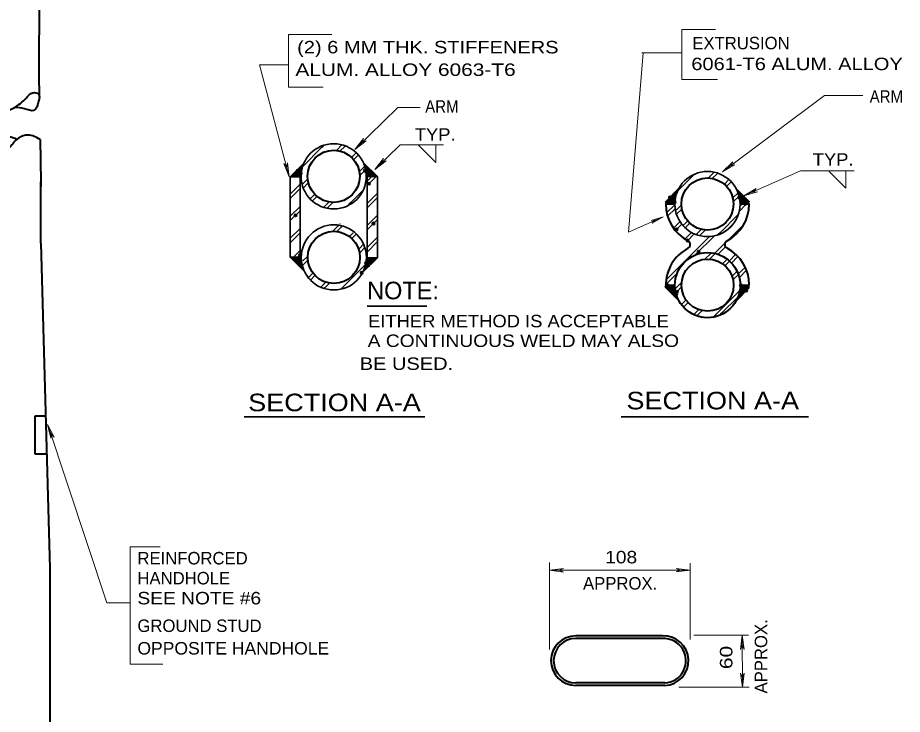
# Model space of a CAD drawing. Extents: x 312583 to 312854, y 144418 to 144597.
# Drawn here: x 312635.8 to 312689.7, y 144489.4 to 144531.9 of the extents above; entities that cross this region are included whole.
import ezdxf
from ezdxf.enums import TextEntityAlignment as Align

# ---------------------------------------------------------------- set-up
doc = ezdxf.new("R2010")
doc.units = 0
doc.header["$LTSCALE"] = 0.3
doc.header["$PDMODE"] = 32
doc.header["$PDSIZE"] = 0.15
doc.layers.add('1', color=7, linetype='Continuous', lineweight=35)

msp = doc.modelspace()

# ---------------------------------------------------------------- linework, layer by layer
at = {"layer": '1', "lineweight": 40}
for p, q in [((312637.0871, 144547.1518), (312637.0642, 144528.44)), ((312637.0642, 144528.44), (312637.0795, 144526.9989)), ((312637.1481, 144524.4369), (312637.1786, 144521.8597)), ((312656.8302, 144523.0071), (312656.8455, 144523.0224)), ((312656.8531, 144522.9385), (312656.8912, 144522.9766)), ((312656.876, 144522.8699), (312656.937, 144522.9309)), ((312652.4535, 144522.1608), (312653.155, 144522.8622)), ((312652.545, 144522.1608), (312653.1016, 144522.7174)), ((312652.6365, 144522.1608), (312653.0635, 144522.5878)), ((312652.7356, 144522.1608), (312653.033, 144522.4658)), ((312656.9065, 144522.8012), (312656.9904, 144522.8851)), ((312656.9294, 144522.7326), (312657.0361, 144522.8394)), ((312656.9522, 144522.664), (312657.0818, 144522.7936)), ((312656.9675, 144522.5878), (312657.1276, 144522.7479)), ((312656.9827, 144522.5039), (312657.1734, 144522.6945)), ((312656.9904, 144522.42), (312657.2191, 144522.6488)), ((312656.998, 144522.3361), (312657.2648, 144522.603)), ((312656.998, 144522.2446), (312657.3106, 144522.5572)), ((312657.0361, 144522.1836), (312657.364, 144522.5115)), ((312657.1276, 144522.1836), (312657.4097, 144522.4658)), ((312657.2191, 144522.1836), (312657.4555, 144522.42)), ((312657.3106, 144522.1836), (312657.5012, 144522.3666)), ((312637.171, 144518.1234), (312637.1786, 144521.8597)), ((312637.1786, 144521.8597), (312637.1862, 144521.5699)), ((312652.8271, 144522.1608), (312653.0254, 144522.359)), ((312652.9186, 144522.1608), (312653.0101, 144522.2522)), ((312657.4021, 144522.1836), (312657.547, 144522.3209)), ((312657.4936, 144522.176), (312657.5927, 144522.2751)), ((312657.5927, 144522.176), (312657.6385, 144522.2294)), ((312657.6842, 144522.176), (312657.6842, 144522.1836)), ((312675.2294, 144520.6281), (312676.0681, 144521.4745)), ((312679.568, 144521.3906), (312679.5832, 144521.4059)), ((312679.5908, 144521.3296), (312679.629, 144521.3601)), ((312679.6214, 144521.261), (312679.6747, 144521.3144)), ((312675.2294, 144520.5366), (312675.9766, 144521.2839)), ((312675.2904, 144520.5061), (312675.9156, 144521.1314)), ((312675.3818, 144520.5061), (312675.8622, 144520.9865)), ((312675.4734, 144520.5061), (312675.8394, 144520.8721)), ((312675.5725, 144520.5061), (312675.8165, 144520.7501)), ((312679.6518, 144521.2), (312679.7205, 144521.2686)), ((312679.6824, 144521.1314), (312679.7662, 144521.2229)), ((312679.6976, 144521.0551), (312679.812, 144521.1771)), ((312679.7128, 144520.9789), (312679.8577, 144521.1238)), ((312679.7281, 144520.9026), (312679.9111, 144521.078)), ((312679.7434, 144520.8188), (312679.9568, 144521.0322)), ((312679.7586, 144520.7425), (312680.0026, 144520.9865)), ((312679.7662, 144520.6586), (312680.0484, 144520.9408)), ((312679.7738, 144520.5748), (312680.0941, 144520.895)), ((312679.7891, 144520.4985), (312680.1398, 144520.8492)), ((312679.8882, 144520.4985), (312680.1856, 144520.8035)), ((312679.9797, 144520.4985), (312680.2314, 144520.7501)), ((312675.664, 144520.5061), (312675.8088, 144520.651)), ((312675.7555, 144520.5061), (312675.7936, 144520.5442)), ((312680.0712, 144520.4985), (312680.2847, 144520.7044)), ((312680.2618, 144520.4985), (312680.3457, 144520.5824)), ((312637.171, 144518.1234), (312637.72, 144498.2908)), ((312652.3848, 144517.2426), (312652.4077, 144517.2579)), ((312652.4306, 144517.1969), (312652.4992, 144517.2579)), ((312652.484, 144517.1511), (312652.5907, 144517.2579)), ((312652.5297, 144517.1054), (312652.6822, 144517.2579)), ((312652.5755, 144517.0596), (312652.7814, 144517.2579)), ((312652.6212, 144517.0062), (312652.8728, 144517.2579)), ((312652.667, 144516.9605), (312652.9644, 144517.2579)), ((312652.7127, 144516.9148), (312653.0254, 144517.2274)), ((312652.7585, 144516.869), (312653.0482, 144517.1588)), ((312652.8042, 144516.8232), (312653.0558, 144517.0749)), ((312652.8576, 144516.7775), (312653.0711, 144516.991)), ((312656.8531, 144516.4801), (312657.608, 144517.235)), ((312656.9141, 144516.6326), (312657.5165, 144517.235)), ((312656.9446, 144516.7546), (312657.425, 144517.235)), ((312656.9751, 144516.8766), (312657.3258, 144517.235)), ((312657.0056, 144517.0978), (312657.1428, 144517.235)), ((312657.0056, 144517.1969), (312657.0437, 144517.2274)), ((312657.0208, 144517.0215), (312657.2344, 144517.235)), ((312652.9034, 144516.7318), (312653.0787, 144516.9071)), ((312652.9491, 144516.6784), (312653.0864, 144516.8156)), ((312652.9948, 144516.6326), (312653.1092, 144516.7546)), ((312653.0406, 144516.5869), (312653.1397, 144516.686)), ((312653.0864, 144516.5411), (312653.1626, 144516.6174)), ((312653.1321, 144516.4954), (312653.1855, 144516.5488)), ((312653.1778, 144516.4496), (312653.216, 144516.4801)), ((312653.2312, 144516.4039), (312653.2465, 144516.4191)), ((312675.2217, 144515.4889), (312675.298, 144515.5651)), ((312675.4276, 144515.2296), (312675.7631, 144515.5651)), ((312675.481, 144515.1839), (312675.8088, 144515.5194)), ((312675.5267, 144515.1381), (312675.8088, 144515.4279)), ((312679.5527, 144514.6272), (312680.361, 144515.4431)), ((312679.6366, 144514.8102), (312680.361, 144515.5346)), ((312679.6976, 144514.9628), (312680.3, 144515.5651)), ((312679.7205, 144515.0771), (312680.2008, 144515.5651)), ((312679.751, 144515.1991), (312680.1094, 144515.5651)), ((312679.7586, 144515.3059), (312680.0178, 144515.5651)), ((312679.7738, 144515.4126), (312679.9264, 144515.5651)), ((312679.7967, 144515.527), (312679.8272, 144515.5651)), ((312675.5725, 144515.0924), (312675.8241, 144515.344)), ((312675.6182, 144515.0466), (312675.8317, 144515.2601)), ((312675.664, 144515.0009), (312675.8546, 144515.1839)), ((312675.7097, 144514.9551), (312675.8698, 144515.1152)), ((312675.7555, 144514.9094), (312675.8927, 144515.039)), ((312675.8088, 144514.856), (312675.9156, 144514.9628)), ((312675.8546, 144514.8102), (312675.9308, 144514.8941)), ((312675.9004, 144514.7645), (312675.9537, 144514.8255)), ((312675.9461, 144514.7188), (312675.9842, 144514.7569)), ((312675.9918, 144514.673), (312676.0071, 144514.6882)), ((312636.8202, 144507.5857), (312636.8202, 144505.2829)), ((312637.4608, 144507.5857), (312636.8202, 144507.5857)), ((312636.8202, 144505.2829), (312637.5218, 144505.2829)), ((312637.72, 144498.2908), (312637.72, 144477.8024)), ((312675.0624, 144494.1835), (312669.7707, 144494.1911)), ((312675.0624, 144494.0234), (312669.7707, 144494.031)), ((312675.1997, 144491.3241), (312669.7707, 144491.3318)), ((312675.1997, 144491.1716), (312669.7707, 144491.1716))]:
    msp.add_line(p, q, dxfattribs=at)
at = {"layer": '1', "lineweight": 13}
for p, q in [((312676.2376, 144528.0969), (312676.2376, 144531.1469)), ((312676.2376, 144531.1469), (312678.2887, 144531.1469)), ((312652.2781, 144527.6279), (312652.2781, 144530.8456)), ((312652.2781, 144530.8456), (312654.9164, 144530.8456)), ((312673.8645, 144529.7185), (312672.98, 144518.7829)), ((312676.2376, 144529.7185), (312673.796, 144529.7185)), ((312676.2376, 144528.0969), (312678.3955, 144528.0969)), ((312652.2781, 144527.6279), (312654.3902, 144527.6279)), ((312656.3041, 144523.823), (312656.8455, 144524.5016)), ((312656.3041, 144523.823), (312656.998, 144524.3491)), ((312656.8455, 144524.5016), (312656.7235, 144524.2348)), ((312656.998, 144524.3491), (312656.7235, 144524.2348)), ((312659.0644, 144524.1204), (312657.5241, 144522.603)), ((312661.7026, 144524.1204), (312659.0644, 144524.1204)), ((312651.9884, 144522.969), (312652.1637, 144522.7326)), ((312652.3162, 144522.1684), (312651.9884, 144522.969)), ((312652.2018, 144523.0224), (312652.1637, 144522.7326)), ((312652.3162, 144522.1684), (312652.2018, 144523.0224)), ((312657.5241, 144522.603), (312658.0578, 144523.2816)), ((312657.5241, 144522.603), (312658.2104, 144523.1291)), ((312658.0578, 144523.2816), (312657.9358, 144523.0148)), ((312658.2104, 144523.1291), (312657.9358, 144523.0148)), ((312678.7064, 144522.4734), (312679.3316, 144523.0681)), ((312679.3316, 144523.0681), (312679.1715, 144522.8241)), ((312678.7064, 144522.4734), (312679.4536, 144522.9004)), ((312679.4536, 144522.9004), (312679.1715, 144522.8241)), ((312683.4644, 144522.5344), (312680.0026, 144521.0018)), ((312686.7278, 144522.5344), (312683.4644, 144522.5344)), ((312685.2028, 144522.4962), (312686.217, 144521.4821)), ((312686.217, 144522.5344), (312686.217, 144521.4821)), ((312652.3696, 144522.1608), (312652.3391, 144522.1836)), ((312680.0026, 144521.0018), (312680.7498, 144521.444)), ((312680.7498, 144521.444), (312680.5364, 144521.2381)), ((312680.0026, 144521.0018), (312680.8337, 144521.2534)), ((312680.8337, 144521.2534), (312680.5364, 144521.2381)), ((312672.98, 144518.7829), (312675.0845, 144519.7284)), ((312675.0845, 144519.7284), (312674.3525, 144519.4996)), ((312675.0845, 144519.7284), (312674.4287, 144519.3319)), ((312674.3525, 144519.4996), (312674.6117, 144519.5149)), ((312674.4287, 144519.3319), (312674.6117, 144519.5149)), ((312637.5904, 144507.0748), (312637.7962, 144506.2284)), ((312637.5904, 144507.0748), (312637.9945, 144506.3047)), ((312641.197, 144496.2016), (312637.6285, 144506.9986)), ((312637.7962, 144506.2284), (312637.7962, 144506.5258)), ((312637.9945, 144506.3047), (312637.7962, 144506.5258)), ((312642.6229, 144499.6252), (312642.6229, 144492.4729)), ((312642.6229, 144499.6252), (312644.4452, 144499.6252)), ((312668.1618, 144493.3676), (312668.1618, 144498.6594)), ((312668.1618, 144498.1866), (312669.0234, 144498.2934)), ((312676.74, 144498.1942), (312668.1618, 144498.1866)), ((312668.1618, 144498.1866), (312669.0234, 144498.0799)), ((312669.0234, 144498.2934), (312668.749, 144498.1866)), ((312669.0234, 144498.0799), (312668.749, 144498.1866)), ((312675.8783, 144498.301), (312676.1528, 144498.1942)), ((312676.74, 144498.1942), (312675.8783, 144498.301)), ((312675.8783, 144498.0875), (312676.1528, 144498.1942)), ((312676.74, 144498.1942), (312675.8783, 144498.0875)), ((312676.7476, 144493.97), (312676.74, 144498.6289)), ((312641.197, 144496.2016), (312642.6229, 144496.2016)), ((312680.2932, 144494.2292), (312676.9534, 144494.2292)), ((312679.912, 144494.2292), (312679.8128, 144493.3676)), ((312679.9196, 144491.0649), (312679.912, 144494.2292)), ((312679.912, 144494.2292), (312680.0263, 144493.3676)), ((312679.8128, 144493.3676), (312679.912, 144493.6421)), ((312680.0263, 144493.3676), (312679.912, 144493.6421)), ((312642.6229, 144492.4729), (312644.6054, 144492.4729)), ((312679.8128, 144491.9265), (312679.9196, 144491.652)), ((312679.9196, 144491.0649), (312679.8128, 144491.9265)), ((312680.0263, 144491.9265), (312679.9196, 144491.652)), ((312679.9196, 144491.0649), (312680.0263, 144491.9265)), ((312680.3313, 144491.0649), (312676.0384, 144491.0649))]:
    msp.add_line(p, q, dxfattribs=at)
at = {"layer": '1'}
for p, q in [((312654.2911, 144523.9602), (312654.4207, 144524.0899)), ((312655.1908, 144523.7772), (312655.5416, 144524.128)), ((312655.4196, 144523.7391), (312655.6788, 144523.9984)), ((312655.6636, 144523.9831), (312655.7322, 144524.0441)), ((312653.1321, 144522.7936), (312654.3064, 144523.9755)), ((312656.1135, 144523.3502), (312656.3498, 144523.5942)), ((312656.2431, 144523.213), (312656.4871, 144523.457)), ((312656.3422, 144523.579), (312656.388, 144523.6324)), ((312656.4642, 144523.4341), (312656.5252, 144523.4951)), ((312652.3696, 144522.1608), (312653.2312, 144523.0224)), ((312657.6918, 144522.176), (312656.8226, 144523.0452)), ((312656.5786, 144522.4734), (312656.8684, 144522.7631)), ((312656.6167, 144522.237), (312656.9065, 144522.5344)), ((312656.8455, 144522.7326), (312656.9065, 144522.8012)), ((312656.8988, 144522.5191), (312656.9675, 144522.5878)), ((312677.86, 144522.0998), (312678.2031, 144522.4429)), ((312678.3556, 144522.3209), (312678.4166, 144522.3895)), ((312652.3696, 144517.2579), (312652.3696, 144522.1608)), ((312652.3696, 144522.1608), (312652.972, 144522.1608)), ((312652.972, 144517.2579), (312652.972, 144522.1608)), ((312657.059, 144517.235), (312657.059, 144522.176)), ((312657.059, 144522.176), (312657.6918, 144522.176)), ((312657.059, 144521.627), (312657.608, 144522.176)), ((312657.059, 144521.8939), (312657.3411, 144522.176)), ((312657.6918, 144517.235), (312657.6918, 144522.176)), ((312675.9614, 144521.2839), (312676.8764, 144522.1989)), ((312676.8458, 144522.1608), (312677.0136, 144522.3361)), ((312678.0811, 144522.054), (312678.3785, 144522.3438)), ((312678.8207, 144521.7109), (312679.1028, 144521.993)), ((312652.3696, 144521.1085), (312652.972, 144521.7109)), ((312652.3696, 144520.8416), (312652.972, 144521.444)), ((312653.1626, 144521.4821), (312653.4905, 144521.81)), ((312655.9762, 144520.5214), (312656.8302, 144521.3678)), ((312675.2294, 144520.6434), (312676.0834, 144521.505)), ((312678.958, 144521.5812), (312679.1944, 144521.8176)), ((312680.3457, 144520.6434), (312679.5451, 144521.444)), ((312653.582, 144520.8264), (312653.8641, 144521.1085)), ((312653.7192, 144520.6891), (312654.0014, 144520.9712)), ((312657.059, 144520.5442), (312657.6918, 144521.1771)), ((312657.059, 144520.2774), (312657.6918, 144520.9102)), ((312679.3316, 144520.8798), (312679.6518, 144521.1924)), ((312679.3774, 144520.651), (312679.6747, 144520.9484)), ((312679.6518, 144520.9255), (312679.7128, 144520.9865)), ((312652.3696, 144519.7589), (312652.972, 144520.3612)), ((312654.4131, 144520.3079), (312654.741, 144520.6358)), ((312654.6266, 144520.2469), (312654.9774, 144520.5976)), ((312655.8466, 144520.3841), (312656.0448, 144520.59)), ((312675.2294, 144520.5061), (312675.7936, 144520.5061)), ((312675.298, 144519.9648), (312675.7936, 144520.4528)), ((312675.3437, 144519.736), (312675.8394, 144520.2316)), ((312675.908, 144520.1478), (312676.1901, 144520.4299)), ((312679.7128, 144520.0562), (312680.1551, 144520.5061)), ((312679.7891, 144520.407), (312679.8806, 144520.4985)), ((312680.3457, 144520.4985), (312679.812, 144520.4985)), ((312652.3696, 144519.492), (312652.972, 144520.0944)), ((312657.059, 144519.1946), (312657.6918, 144519.8351)), ((312675.847, 144520.0868), (312675.9232, 144520.163)), ((312675.908, 144519.8809), (312676.2282, 144520.2011)), ((312678.5386, 144518.7295), (312679.6671, 144519.8656)), ((312655.3281, 144519.2251), (312654.9316, 144518.821)), ((312655.2061, 144518.8286), (312655.534, 144519.1565)), ((312655.2442, 144519.1336), (312655.3205, 144519.2175)), ((312655.412, 144519.3014), (312655.4044, 144519.3014)), ((312655.4806, 144519.1031), (312655.5416, 144519.1718)), ((312657.059, 144518.9278), (312657.6918, 144519.5606)), ((312675.7097, 144519.0192), (312676.1215, 144519.431)), ((312675.8241, 144518.8668), (312676.2282, 144519.2709)), ((312676.2968, 144519.1946), (312676.3578, 144519.2556)), ((312676.335, 144519.2251), (312676.579, 144519.4691)), ((312676.4341, 144519.0574), (312676.7162, 144519.3319)), ((312680.0178, 144519.2785), (312679.0037, 144518.272)), ((312679.019, 144518.9506), (312679.3468, 144519.2709)), ((312652.3696, 144518.4169), (312652.972, 144519.0116)), ((312652.3696, 144518.1424), (312652.972, 144518.7448)), ((312656.2126, 144518.76), (312655.9838, 144518.5312)), ((312656.1211, 144518.4016), (312656.4032, 144518.6838)), ((312676.4112, 144518.3711), (312676.8154, 144518.7752)), ((312676.5714, 144518.2644), (312676.9907, 144518.6838)), ((312677.0975, 144518.6456), (312677.1585, 144518.7066)), ((312677.1432, 144518.6838), (312677.4254, 144518.9659)), ((312677.3034, 144518.577), (312677.6465, 144518.9201)), ((312678.4318, 144518.6228), (312678.5767, 144518.7752)), ((312657.059, 144517.8526), (312657.6918, 144518.4855)), ((312657.059, 144517.5781), (312657.6918, 144518.2186)), ((312675.2598, 144515.8701), (312677.9057, 144518.5236)), ((312677.0517, 144517.4028), (312678.2031, 144518.5465)), ((312678.8741, 144518.1424), (312678.2336, 144517.5019)), ((312652.5678, 144517.2579), (312652.972, 144517.6696)), ((312656.5481, 144517.7459), (312656.8455, 144518.0509)), ((312656.6091, 144517.54), (312656.9217, 144517.8526)), ((312677.9438, 144517.4561), (312678.0277, 144517.5324)), ((312678.4471, 144517.4485), (312678.8741, 144517.8755)), ((312652.3696, 144517.2579), (312652.972, 144517.2579)), ((312652.3696, 144517.2579), (312653.2694, 144516.3658)), ((312652.8347, 144517.2579), (312652.972, 144517.3951)), ((312653.1092, 144516.7394), (312653.4524, 144517.0825)), ((312653.4447, 144517.3341), (312653.1474, 144517.0444)), ((312657.6918, 144517.235), (312656.8226, 144516.3658)), ((312657.059, 144517.235), (312657.6918, 144517.235)), ((312677.6388, 144517.1511), (312677.9667, 144517.479)), ((312677.9057, 144517.1511), (312678.2565, 144517.4942)), ((312678.7064, 144516.869), (312678.9427, 144517.1054)), ((312678.8588, 144516.747), (312679.1334, 144517.0291)), ((312678.9275, 144517.0901), (312678.9885, 144517.1511)), ((312679.1257, 144517.0444), (312679.507, 144517.4256)), ((312679.2554, 144516.9071), (312679.629, 144517.2808)), ((312655.5035, 144515.3516), (312656.9675, 144516.8156)), ((312679.6671, 144516.2438), (312680.0788, 144516.6479)), ((312679.7357, 144516.0379), (312680.1704, 144516.4725)), ((312653.4752, 144516.0226), (312653.5286, 144516.076)), ((312653.765, 144516.3124), (312653.4828, 144516.0302)), ((312653.5972, 144515.8778), (312653.6582, 144515.9311)), ((312653.6201, 144515.893), (312653.8717, 144516.1522)), ((312675.2217, 144515.5651), (312675.969, 144516.3124)), ((312679.2858, 144516.0989), (312679.5527, 144516.3658)), ((312679.3545, 144515.9006), (312679.6747, 144516.2209)), ((312679.5298, 144516.3505), (312679.5908, 144516.4115)), ((312654.2377, 144515.4355), (312654.5427, 144515.7405)), ((312654.2377, 144515.4355), (312654.3064, 144515.5041)), ((312654.4284, 144515.3592), (312654.4894, 144515.4202)), ((312654.436, 144515.3669), (312654.7562, 144515.6871)), ((312655.4654, 144515.3135), (312655.6026, 144515.4584)), ((312675.2217, 144515.5651), (312675.7784, 144515.5651)), ((312675.2217, 144515.4431), (312676.03, 144514.6349)), ((312675.8241, 144515.3364), (312676.213, 144515.7252)), ((312675.9156, 144515.161), (312676.2054, 144515.4508)), ((312680.361, 144515.4279), (312679.5298, 144514.5968)), ((312680.361, 144515.5651), (312679.8044, 144515.5651)), ((312680.3381, 144515.5651), (312680.361, 144515.588)), ((312675.8698, 144515.1076), (312675.9308, 144515.1762)), ((312678.1421, 144513.6131), (312679.6747, 144515.1458)), ((312678.6454, 144513.8495), (312679.6518, 144514.8484)), ((312679.6518, 144515.1152), (312679.751, 144515.222)), ((312657.0639, 144514.2808), (312660.701, 144514.2808)), ((312676.213, 144514.3756), (312676.5027, 144514.6654)), ((312676.3655, 144514.2612), (312676.6095, 144514.4976)), ((312676.335, 144514.2231), (312676.3884, 144514.2765)), ((312676.9526, 144513.7656), (312677.2576, 144514.0706)), ((312677.1432, 144513.6894), (312677.2118, 144513.758)), ((312677.189, 144513.7351), (312677.4711, 144514.0172)), ((312678.5157, 144513.7122), (312678.6758, 144513.8724)), ((312649.5759, 144507.5436), (312660.5714, 144507.5436)), ((312672.5423, 144507.5436), (312683.9368, 144507.5436))]:
    msp.add_line(p, q, dxfattribs=at)
at = {"layer": '1', "lineweight": 13}
for points in [[(312652.2781, 144528.9851), (312650.4938, 144528.9851), (312652.3162, 144522.1684)], [(312687.254, 144527.1246), (312684.9207, 144527.1246), (312678.7064, 144522.4734)], [(312660.292, 144526.385), (312658.9195, 144526.385), (312656.3041, 144523.823)], [(312660.1776, 144524.1204), (312661.2527, 144523.0376), (312661.2527, 144524.1204)]]:
    msp.add_lwpolyline(points, dxfattribs=at)
at = {"layer": '1'}
for points in [[(312653.1474, 144521.7338), (312653.1016, 144521.688), (312653.4447, 144522.0388)], [(312679.1791, 144521.8024), (312679.2401, 144521.8634), (312679.2401, 144521.8634)]]:
    msp.add_lwpolyline(points, dxfattribs=at)
at = {"layer": '1', "lineweight": 40}
for points in [[(312680.1704, 144520.4985), (312680.3305, 144520.6586), (312680.3305, 144520.6586)], [(312675.2446, 144515.4202), (312675.2446, 144515.4202), (312675.3895, 144515.5651)], [(312675.2904, 144515.3745), (312675.2904, 144515.3745), (312675.481, 144515.5651)], [(312675.3361, 144515.3288), (312675.3361, 144515.3288), (312675.5801, 144515.5651)], [(312675.3818, 144515.2754), (312675.3818, 144515.2754), (312675.6716, 144515.5651)]]:
    msp.add_lwpolyline(points, dxfattribs=at)
at = {"layer": '1'}
for centre in [(312655.0206, 144522.1938), (312677.7901, 144520.5049), (312655.0288, 144517.2534)]:
    msp.add_circle(centre, 1.9857, dxfattribs=at)
at = {"layer": '1', "lineweight": 40}
for centre, radius in [((312655.0206, 144522.1938), 1.5885), ((312677.7901, 144520.5049), 1.5885), ((312655.0288, 144517.2534), 1.5885), ((312677.7983, 144515.5645), 1.9857), ((312677.7983, 144515.5645), 1.5885)]:
    msp.add_circle(centre, radius, dxfattribs=at)
for centre, radius, start, end in [((312677.7901, 144520.5049), 2.5417, 179.98549, 242.16622), ((312677.7901, 144520.5049), 2.5417, 298.02538, 359.64884), ((312676.4847, 144518.0325), 0.2542, 298.02537, 62.16622), ((312679.1037, 144518.0369), 0.2542, 118.02538, 242.16622), ((312677.7983, 144515.5645), 2.5417, 118.02538, 180.9673), ((312677.7983, 144515.5645), 2.5417, 0.19598, 62.16622), ((312669.7685, 144492.6811), 1.5091, 89.96381, 269.9397), ((312669.7685, 144492.6811), 1.3503, 89.95955, 269.93261), ((312675.1279, 144492.6769), 1.511, 272.74469, 92.55551), ((312675.1279, 144492.6769), 1.3521, 272.74469, 92.85568)]:
    msp.add_arc(centre, radius, start, end, dxfattribs=at)
for points in [[(312634.1896, 144526.6634), (312634.7844, 144526.183), (312635.5088, 144526.3432), (312635.9358, 144526.6406), (312636.2865, 144526.9608), (312636.6906, 144527.281), (312637.0414, 144527.2048), (312637.0414, 144526.7702), (312636.744, 144526.2059), (312636.1798, 144526.3127), (312635.6155, 144526.3966)], [(312637.1481, 144524.4369), (312636.4085, 144524.7114), (312635.8138, 144524.5208), (312635.524, 144524.2539), (312635.3105, 144523.987), (312635.036, 144523.8803), (312634.4184, 144523.8803), (312634.1515, 144524.1167), (312634.2888, 144524.4369), (312634.6929, 144524.6809), (312635.2266, 144524.6276), (312635.707, 144524.4674)]]:
    msp.add_spline(points, degree=3, dxfattribs=at)
at = {"layer": '1'}
for p in [(312652.8271, 144522.5344), (312652.8728, 144522.4886), (312652.9186, 144522.4429), (312652.9644, 144522.3971), (312653.0177, 144522.3514), (312656.9294, 144522.5496), (312656.9827, 144522.5039), (312657.0285, 144522.4581), (312657.0742, 144522.4124), (312657.1276, 144522.3666), (312657.1734, 144522.3209), (312657.2191, 144522.2751), (312657.2648, 144522.2294), (312657.1734, 144521.7414), (312675.5115, 144520.9179), (312675.5648, 144520.8721), (312675.6106, 144520.8264), (312675.6564, 144520.7806), (312675.7021, 144520.7349), (312675.7478, 144520.6815), (312679.7357, 144520.9102), (312679.7815, 144520.8645), (312679.8272, 144520.8111), (312679.873, 144520.7654), (312679.9187, 144520.7196), (312679.9721, 144520.6739), (312675.7936, 144520.6358), (312680.0178, 144520.6281), (312680.0636, 144520.5824), (312680.1094, 144520.5366), (312652.6975, 144519.8199), (312657.4478, 144519.3166), (312675.9156, 144518.9582), (312676.5866, 144518.2796), (312677.2576, 144517.6086), (312652.972, 144517.3951), (312656.998, 144516.9071), (312657.0437, 144516.8538), (312657.0895, 144516.808), (312657.1352, 144516.7622), (312656.7311, 144516.3124), (312675.3666, 144515.5422), (312675.4124, 144515.4965), (312675.4581, 144515.4508), (312675.5038, 144515.405), (312675.5572, 144515.3592), (312675.603, 144515.3059), (312679.8272, 144515.5575), (312679.873, 144515.5118), (312679.9187, 144515.466), (312679.9645, 144515.4202), (312680.0102, 144515.3669), (312680.056, 144515.3211), (312675.6487, 144515.2601), (312675.6945, 144515.2144), (312675.7402, 144515.1686), (312675.786, 144515.1229), (312675.8317, 144515.0771), (312675.8851, 144515.0314), (312675.9308, 144515.1686), (312680.1017, 144515.2754), (312680.1551, 144515.2296)]:
    msp.add_point(p, dxfattribs=at)

# ---------------------------------------------------------------- texts
for s, width, p in [('(2) 6 MM THK. STIFFENERS', 1.2, (312652.7966, 144529.6852)), ('6061-T6 ALUM. ALLOY', 1.2, (312676.8088, 144528.6633)), ('ALUM. ALLOY 6063-T6', 1.25, (312652.6905, 144528.3112)), ('ARM', 0.9, (312687.6748, 144526.6777)), ('ARM', 0.9, (312660.597, 144526.0695)), ('TYP.', 1.1, (312659.9641, 144524.3628)), ('TYP.', 1.1, (312684.205, 144522.8392)), ('EITHER METHOD IS ACCEPTABLE', 1.1, (312657.116, 144512.9926)), ('A CONTINUOUS WELD MAY ALSO', 1.15, (312657.0939, 144511.7948)), (' BE USED.', 1.2, (312656.2682, 144510.3974)), ('108 ', 1.15, (312671.5588, 144498.6087)), ('SEE NOTE #6', 1.15, (312643.0651, 144496.1099)), ('OPPOSITE HANDHOLE', 1.05, (312643.0651, 144493.0549))]:
    msp.add_text(s, height=0.76, dxfattribs=dict(at, width=width)).set_placement(p)
for s, p in [('EXTRUSION', (312676.8675, 144529.9327)), ('REINFORCED', (312643.0651, 144498.5449)), ('HANDHOLE', (312643.0651, 144497.3274)), ('APPROX.', (312670.2114, 144497.0139)), ('GROUND STUD', (312643.0651, 144494.4274))]:
    msp.add_text(s, height=0.76, dxfattribs=at).set_placement(p)
msp.add_text('NOTE:', height=1.07, dxfattribs=at).set_placement((312659.2442, 144514.7014), align=Align.CENTER)
at = {"layer": '1', "width": 1.15}
for p in [(312655.0693, 144507.8796), (312678.112, 144507.9934)]:
    msp.add_text('SECTION A-A', height=1.07, dxfattribs=at).set_placement(p, align=Align.CENTER)
at = {"layer": '1'}
msp.add_text('APPROX.', height=0.76, rotation=90, dxfattribs=at).set_placement((312681.4296, 144490.6829))
at = {"layer": '1', "width": 1.25}
msp.add_text('60 ', height=0.76, rotation=90, dxfattribs=at).set_placement((312679.3105, 144492.1676))

doc.saveas('drawing.dxf')
